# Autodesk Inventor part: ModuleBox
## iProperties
Company: Autodes, Inc
Created: 2005-03
Part Number: ModuleBox
Document SubType Name: Modeling
Density: 1 g/cm^3
Author: Admin
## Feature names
1. Extrusion1
2. Fillet1
3. Shell1
4. Extrusion2
5. Fillet2
6. Extrusion3
7. Fillet3
8. Extrusion4
9. Fillet4
10. Fillet5
